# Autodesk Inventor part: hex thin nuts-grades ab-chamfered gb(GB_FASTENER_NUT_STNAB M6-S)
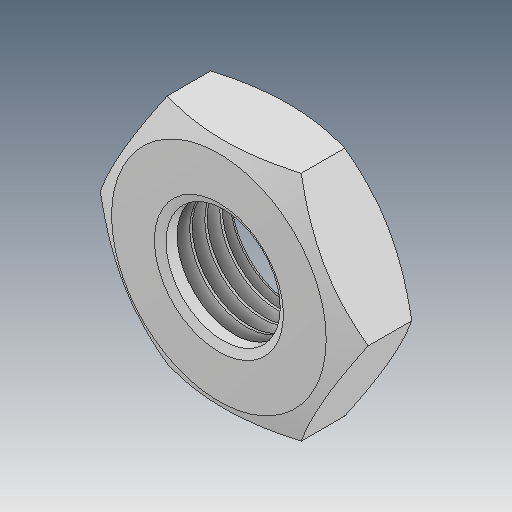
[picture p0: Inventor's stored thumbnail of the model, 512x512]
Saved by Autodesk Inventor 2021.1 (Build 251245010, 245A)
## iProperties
Created: 2021-05
Part Number: hex thin nuts-grades ab-chamfered gb(GB_FASTENER_NUT_STNAB M6-S)
Material: Ogólny
Document SubType Name: Modeling
Designer: user
Density: 1 g/cm^3
Appearance: Domyślna
Author: user
Revision Number: ÈÎºÎ
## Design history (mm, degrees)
feature "ÊäÈë1"
node "Bryła1"
